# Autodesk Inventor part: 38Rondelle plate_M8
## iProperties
Created: 2011-01
Part Number: 38Rondelle plate_M8
Document SubType Name: Modeling
Designer: eric
Density: 1 g/cm^3
Mass: 0.194075 g
Surface Area: 3.60215 cm^2
Volume: 0.194075 cm^3
Author: eric
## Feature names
1. Base1
